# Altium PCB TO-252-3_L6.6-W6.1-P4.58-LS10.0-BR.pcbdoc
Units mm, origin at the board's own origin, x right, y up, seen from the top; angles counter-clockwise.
Board outline 24.18 x 19.92 mm, 2 copper layers (Top Layer, Bottom Layer), stack 0 mm thick; 1 components, 0 nets, 3 pads, 0 vias.
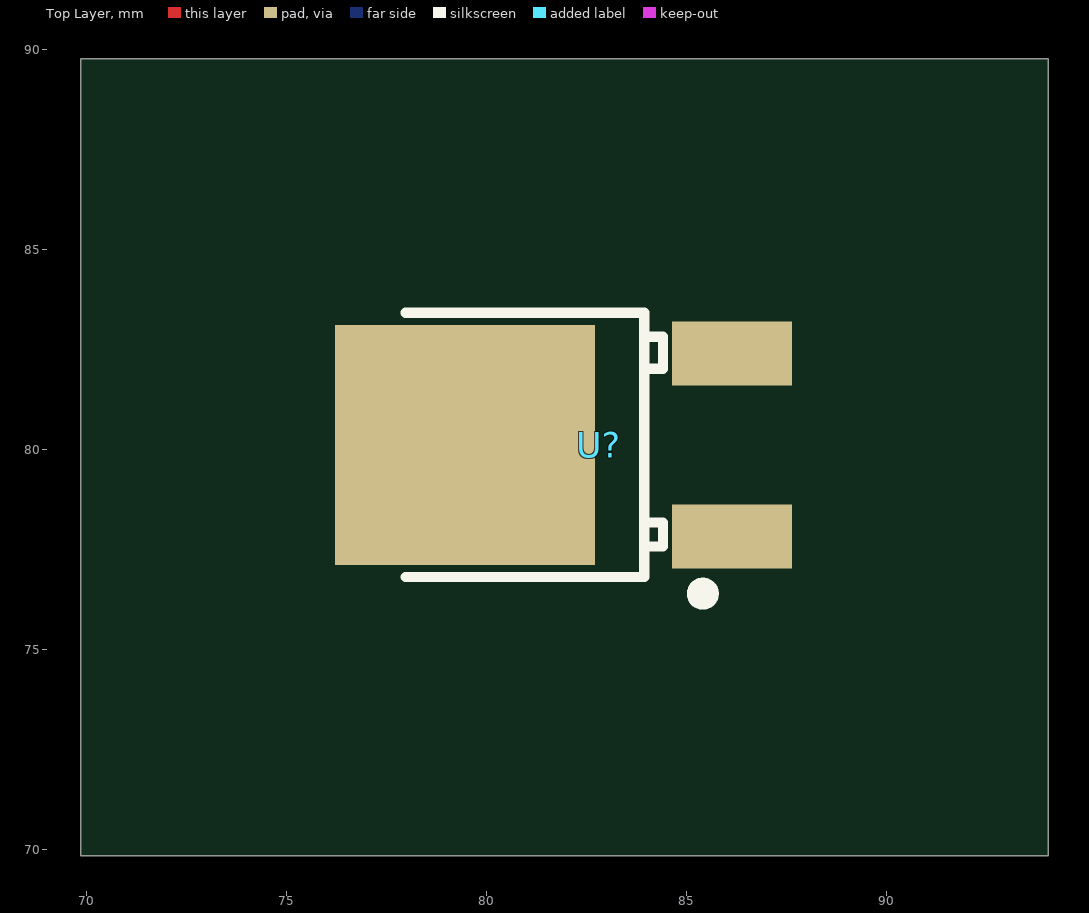
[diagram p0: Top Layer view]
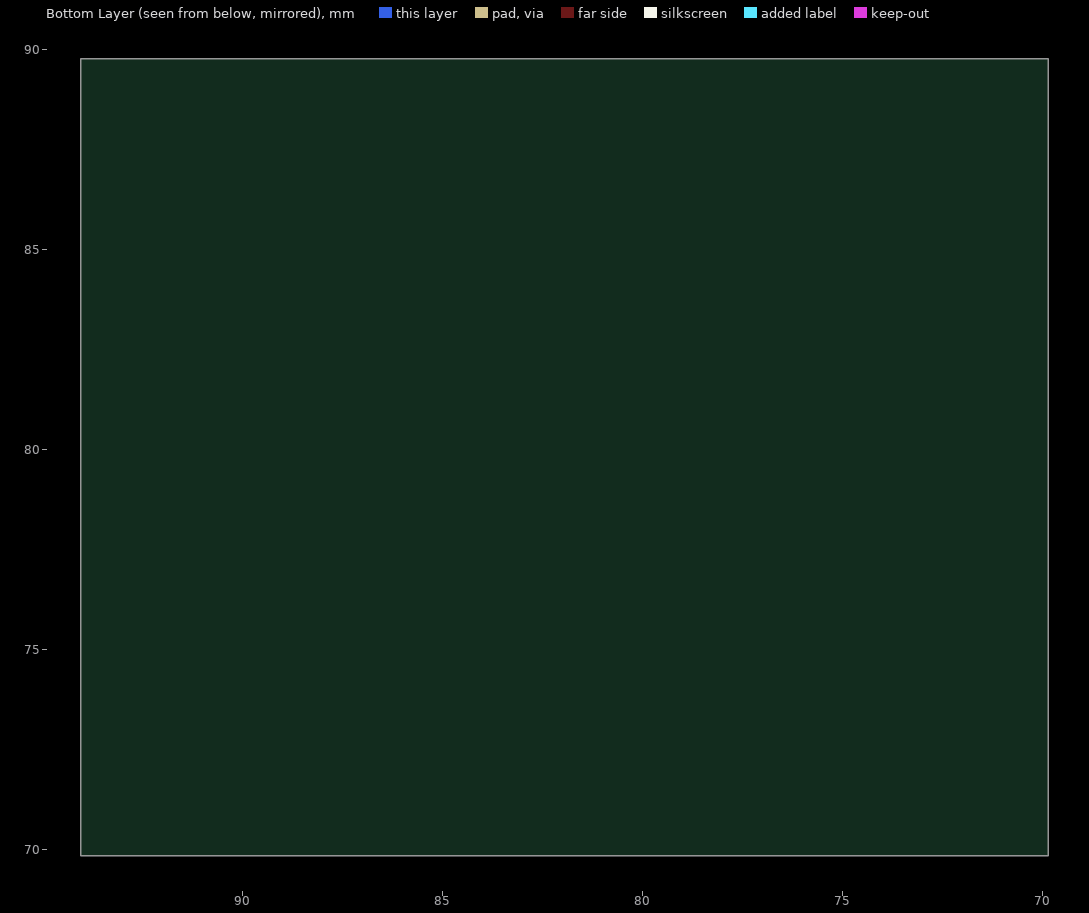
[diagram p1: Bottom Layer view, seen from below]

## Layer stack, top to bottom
Top Layer: signal copper (thickness not stored)
Bottom Layer: signal copper (thickness not stored)

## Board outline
94.03,69.85 69.85,69.85 69.85,89.772 94.03,89.772

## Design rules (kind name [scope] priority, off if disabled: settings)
PasteMaskExpansion "Paste Mask Expansion" [All] p1: expansion=0
SolderMaskExpansion "Solder Mask Expansion" [IsVia] p1: expansion=-25.4 istentingtop=TRUE
SolderMaskExpansion "Solder Mask Expansion" [All] p2: expansion=0.051 istentingtop=FALSE

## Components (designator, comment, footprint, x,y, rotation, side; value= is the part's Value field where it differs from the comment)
U? "" TO-252-3_L6.6-W6.1-P4.58-LS10.0-BR 82.793,80.12 r0 top

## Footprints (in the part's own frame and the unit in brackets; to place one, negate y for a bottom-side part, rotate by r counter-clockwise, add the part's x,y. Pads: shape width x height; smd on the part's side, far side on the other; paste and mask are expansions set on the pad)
TO-252-3_L6.6-W6.1-P4.58-LS10.0-BR [mm]
  rect 3x1.6 smd: 1(3.342,-2.285) 2(3.342,2.285)
  rect 6.5x6 smd: 3(-3.343,0)
  silkscreen extent -4.83,-3.92 2.81,3.3

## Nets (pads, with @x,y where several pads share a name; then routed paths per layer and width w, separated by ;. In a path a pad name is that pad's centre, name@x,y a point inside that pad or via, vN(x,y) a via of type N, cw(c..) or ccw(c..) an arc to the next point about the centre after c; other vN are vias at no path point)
pads on no net: U?.1 U?.2 U?.3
